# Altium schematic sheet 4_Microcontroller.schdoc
size 309 x 223 mm; Symbol: Sheet-Symbol_A4; Device: Sheet-Symbol_A4; @Project Name: V2 - ODrive Rev Motor Module; @Page Count: 5; @Update Date: 2024-12-31; @Create Date: 2024-12-04; @Schematic Name: Schematic-A; @Page No: 4; @Page Name: Microcontroller; Company: EasyEDA.com; Reviewed: EasyEDA; Version: V0.1; Page Size: A4; Part Number: JLCPCB-002; Drawn: EasyEDA; @Board Name: BaseModule; @Create Time: 20:02:26; @Update Time: 16:24:46
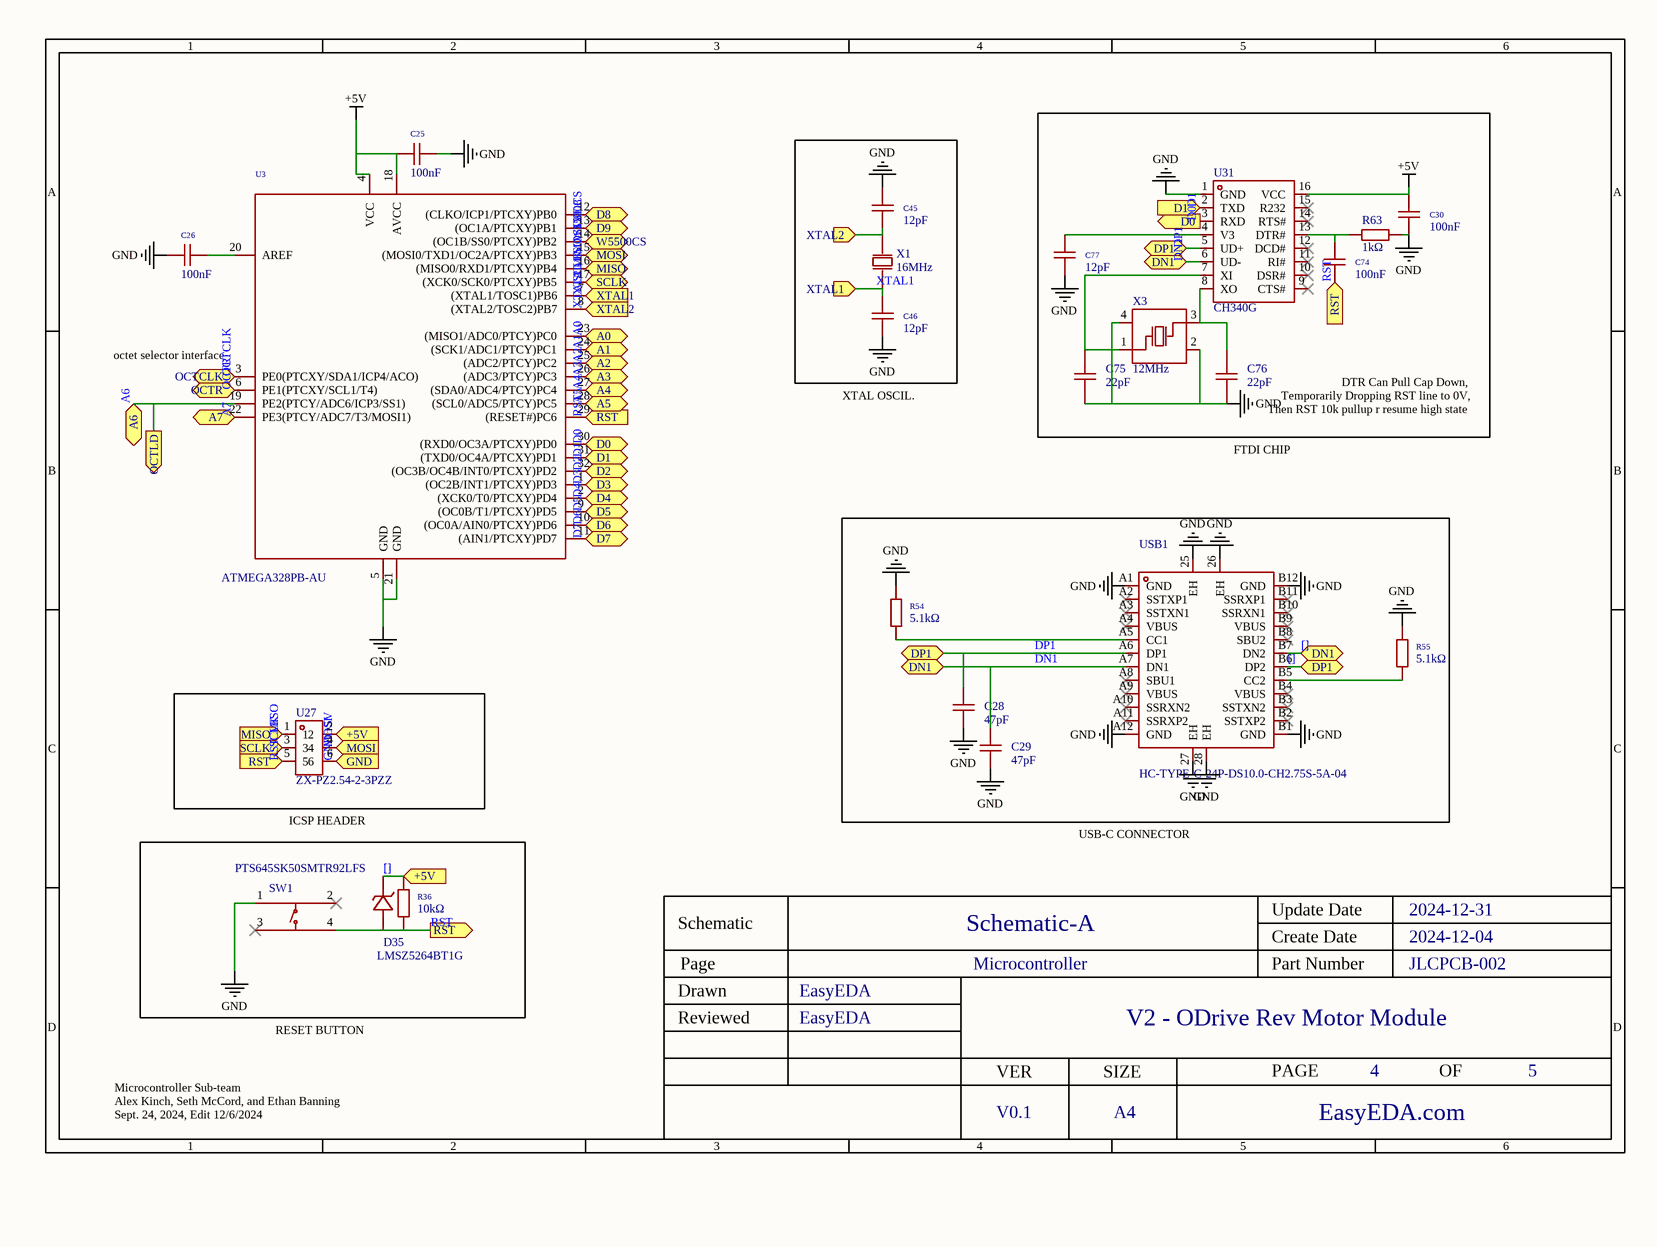
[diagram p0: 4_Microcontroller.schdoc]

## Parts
C25  100nF  [C0805]
C26  100nF  [C0805]
C28  47pF  [C0805]
C29  47pF  [C0805]
C30  100nF  [C0805]
C45  12pF  [C0402]
C46  12pF  [C0402]
C74  100nF  [C0805]
C75  22pF  [C01005]
C76  22pF  [C01005]
C77  12pF  [C0402]
D35  LMSZ5264BT1G  [SOD-123_L2.7-W1.6-LS3.7-RD-1]
R36  10kΩ  [R0805]
R54  5.1kΩ  [R0402]
R55  5.1kΩ  [R0402]
R63  1kΩ  [R0805]
SW1  PTS645SK50SMTR92LFS  [KEY-SMD_4P-L6.0-W6.0-P4.50-LS9.0]
U3  ATMEGA328PB-AU  [TQFP-32_L7.0-W7.0-P0.80-LS9.0-BL]
U27  ZX-PZ2.54-2-3PZZ  [HDR-TH_6P-P2.54-V-M-R2-C3-S2.54-1]
U31  CH340G  [SOIC-16_L9.9-W3.9-P1.27-LS6.0-BL]
USB1  HC-TYPE-C-24P-DS10.0-CH2.75S-5A-04  [USB-TYPE-C-SMD_HC-TYPE-C-24P-DS10.0-CH2.75S-5A-04]
X1  16MHz  [HC-49S_L11.4-W4.8]
X3  12MHz  [CRYSTAL-SMD_4P-L3.2-W2.5-BL]

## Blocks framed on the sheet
ICSP HEADER: D35 R36 SW1

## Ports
+5V (in), A0 (bidir), A1 (bidir), A2 (bidir), A3 (bidir), A4 (bidir), A5 (bidir), A6 (bidir), A7 (bidir), D0 (bidir), D0 (out), D1 (bidir), D1 (in), D2 (bidir), D3 (bidir), D4 (bidir), D5 (bidir), D6 (bidir), D7 (bidir), D8 (bidir), D9 (bidir), DN1 (bidir), DP1 (bidir), GND (in), MISO (bidir), MISO (in), MOSI (bidir), MOSI (in), OCTCLK (bidir), OCTLD (out), OCTR (bidir), RST (in), RST (out), SCLK (bidir), SCLK (in), W5500CS (bidir), XTAL1 (in), XTAL2 (in)

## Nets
+5V: C25.1 C28.2 C29.2 C30.1 D35.1(C) R36.1 U3.4(VCC) U3.18(AVCC) U27.2 U31.5(UD+) U31.6(UD-) U31.16(VCC) USB1.A6(DP1) USB1.A7(DN1) USB1.B6(DP2) USB1.B7(DN2) ; port +5V, port DN1, port DP1  [also labelled [], DN1, DP1]
GND: C25.2 C26.1 C28.1 C29.1 C30.2 C45.2 C46.1 C75.1 C76.1 C77.1 R54.2 R55.2 R63.2 SW1.1 U3.5(GND) U3.21(GND) U27.6 U31.1(GND) USB1.25(EH) USB1.26(EH) USB1.27(EH) USB1.28(EH) USB1.A1(GND) USB1.A12(GND) USB1.B1(GND) USB1.B12(GND) X3.2(GND) X3.4(GND) ; port GND
A0: U3.23((MISO1/ADC0/PTCY)PC0) ; port A0
A1: U3.24((SCK1/ADC1/PTCY)PC1) ; port A1
A2: U3.25((ADC2/PTCY)PC2) ; port A2
A3: U3.26((ADC3/PTCY)PC3) ; port A3
A4: U3.27((SDA0/ADC4/PTCY)PC4) ; port A4
A5: U3.28((SCL0/ADC5/PTCY)PC5) ; port A5
A6: U3.19(PE2(PTCY/ADC6/ICP3/SS1)) ; port A6, port OCTLD
A7: U3.22(PE3(PTCY/ADC7/T3/MOSI1)) ; port A7
D0: U3.30((RXD0/OC3A/PTCXY)PD0) U31.3(RXD) ; port D0
D1: U3.31((TXD0/OC4A/PTCXY)PD1) U31.2(TXD) ; port D1
D2: U3.32((OC3B/OC4B/INT0/PTCXY)PD2) ; port D2
D3: U3.1((OC2B/INT1/PTCXY)PD3) ; port D3
D4: U3.2((XCK0/T0/PTCXY)PD4) ; port D4
D5: U3.9((OC0B/T1/PTCXY)PD5) ; port D5
D6: U3.10((OC0A/AIN0/PTCXY)PD6) ; port D6
D7: U3.11((AIN1/PTCXY)PD7) ; port D7
D8: U3.12((CLKO/ICP1/PTCXY)PB0) ; port D8
D9: U3.13((OC1A/PTCXY)PB1) ; port D9
MISO: U3.16((MISO0/RXD1/PTCXY)PB4) U27.1 ; port MISO
MOSI: U3.15((MOSI0/TXD1/OC2A/PTCXY)PB3) U27.4 ; port MOSI
OCTCLK: U3.3(PE0(PTCXY/SDA1/ICP4/ACO)) ; port OCTCLK
OCTR: U3.6(PE1(PTCXY/SCL1/T4)) ; port OCTR
RST: C74.1 D35.2(A) R36.2 SW1.4 U3.29((RESET#)PC6) U27.5 ; port RST
SCLK: U3.17((XCK0/SCK0/PTCXY)PB5) U27.3 ; port SCLK
W5500CS: U3.14((OC1B/SS0/PTCXY)PB2) ; port W5500CS
XTAL1: C46.2 U3.7((XTAL1/TOSC1)PB6) X1.1(OSC1) ; port XTAL1
XTAL2: C45.1 U3.8((XTAL2/TOSC2)PB7) X1.2(OSC2) ; port XTAL2
NetC26_2: C26.2 U3.20(AREF)
NetC74_2: C74.2 R63.1 U31.13(DTR#)
NetC75_2: C75.2 U31.7(XI) X3.1(OSC1)
NetC76_2: C76.2 U31.8(XO) X3.3(OSC2)
NetC77_2: C77.2 U31.4(V3)
NetR54_1: R54.1 USB1.A5(CC1)
NetR55_1: R55.1 USB1.B5(CC2)

Not connected (* = marked no-connect by the designer): SW1 2* 3*; U31 9(CTS#)* 10(DSR#)* 11(RI#)* 12(DCD#)* 14(RTS#)* 15(R232)*; USB1 A2(SSTXP1)* A3(SSTXN1)* A4(VBUS)* A8(SBU1)* A9(VBUS)* A10(SSRXN2)* A11(SSRXP2)* B2(SSTXP2)* B3(SSTXN2)* B4(VBUS)* B8(SBU2)* B9(VBUS)* B10(SSRXN1)* B11(SSRXP1)*

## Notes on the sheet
- (near U3) octet selector interface
- XTAL OSCIL.
- (near C76) Then RST 10k pullup r resume high state
- Temporarily Dropping RST line to 0V,
- DTR Can Pull Cap Down,
- FTDI CHIP
- USB-C CONNECTOR
- Microcontroller Sub-team
  Alex Kinch, Seth McCord, and Ethan Banning
  Sept. 24, 2024, Edit 12/6/2024
- RESET BUTTON

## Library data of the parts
C25 C26 C30 C74 = 0805B104K500NT: Manufacturer: FH(风华); Add into BOM: yes; Tolerance: ±10%
C28 C29 = CL21C470JBANNNC: Manufacturer: SAMSUNG(三星); Add into BOM: yes; Tolerance: ±5%
C45 C46 C77 = CC0402JRNPO9BN120: Manufacturer: YAGEO(国巨); Add into BOM: yes; Tolerance: ±5%
C75 C76 = GRM0225C1E220JA02L: Manufacturer: muRata(村田); Add into BOM: yes; Tolerance: ±5%
D35 = LMSZ5264BT1G: Manufacturer: LRC(乐山无线电); Add into BOM: yes; Diode Configuration: Single; Zener Voltage (Nom): 60V; Reverse Leakage Current (Ir): 2.1mA; Zener Voltage (Range): 57V~63V; Power Dissipation: 500mW; Zener Impedance (Zzt): 170Ω; Tolerance: ±5%
R36 = 0805W8F1002T5E: Manufacturer: UNI-ROYAL(厚声); Add into BOM: yes; Tolerance: ±1%; Temperature Coefficient: ±100ppm/℃
R54 R55 = 0402WGF5101TCE: Manufacturer: UNI-ROYAL(厚声); Add into BOM: yes; Tolerance: ±1%; Temperature Coefficient: ±100ppm/℃
R63 = 0805W8F1001T5E: Manufacturer: UNI-ROYAL(厚声); Add into BOM: yes; Tolerance: ±1%; Temperature Coefficient: ±100ppm/℃
SW1 = PTS645SK50SMTR92LFS: Manufacturer: C&K; Add into BOM: yes; Circuit: SPST; Actuator Style: Round Button; Operating Force: 260gf; Switch Length: 6mm; Switch Height: 1.55mm; Contact Current: 50mA; Voltage Rating (DC): 12V; Pin Style: Gull Wing
U3 = ATMEGA328PB-AU: Manufacturer: MICROCHIP(美国微芯); Add into BOM: yes; CPU Core: AVR; Program Storage Size: 32KB; RAM Size: 2KB; GPIO Ports Number: 27; Operating Voltage Range: 1.8V~5.5V; CPU Maximum Speed: 20MHz; Program Memory Type: FLASH; ADC (Bit): 10bit; Watchdog: 有
U27 = ZX-PZ2.54-2-3PZZ: Manufacturer: Megastar(兆星); Add into BOM: yes; Pin Structure: 2x3P; Pitch: 2.54mm; Circluar Pins/Square Pins: Square Pins; Current Rating (Max): 3A; Voltage Rating (Max): 1kV
U31 = CH340G: Manufacturer: WCH(南京沁恒); Add into BOM: yes; Applications Function: USB to UART; Supply Voltage: 5V；3.3V; Data Rate: 2Mbps
USB1 = HC-TYPE-C-24P-DS10.0-CH2.75S-5A-04: Manufacturer: HCTL(华灿天禄); Add into BOM: yes; Connector Type: Type-C; Gender: Female; Number of Contacts: 24P; Number of Ports: 1; Current Rating - Power (Max): 5A; Soldering Temperature(Max): 260℃
X1 = X49SM16MSD2SC: Manufacturer: YXC(扬兴晶振); Add into BOM: yes; Crystal Type: Surface Mount Crystal; Normal temperature Frequency Tolerance: ±20ppm; Frequency Stability(Full temperature range): ±30ppm
X3 = X322512MOB4SI: Manufacturer: YXC(扬兴晶振); Add into BOM: yes; Crystal Type: Surface Mount Crystal; Normal temperature Frequency Tolerance: ±10ppm; Frequency Stability(Full temperature range): ±20ppm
